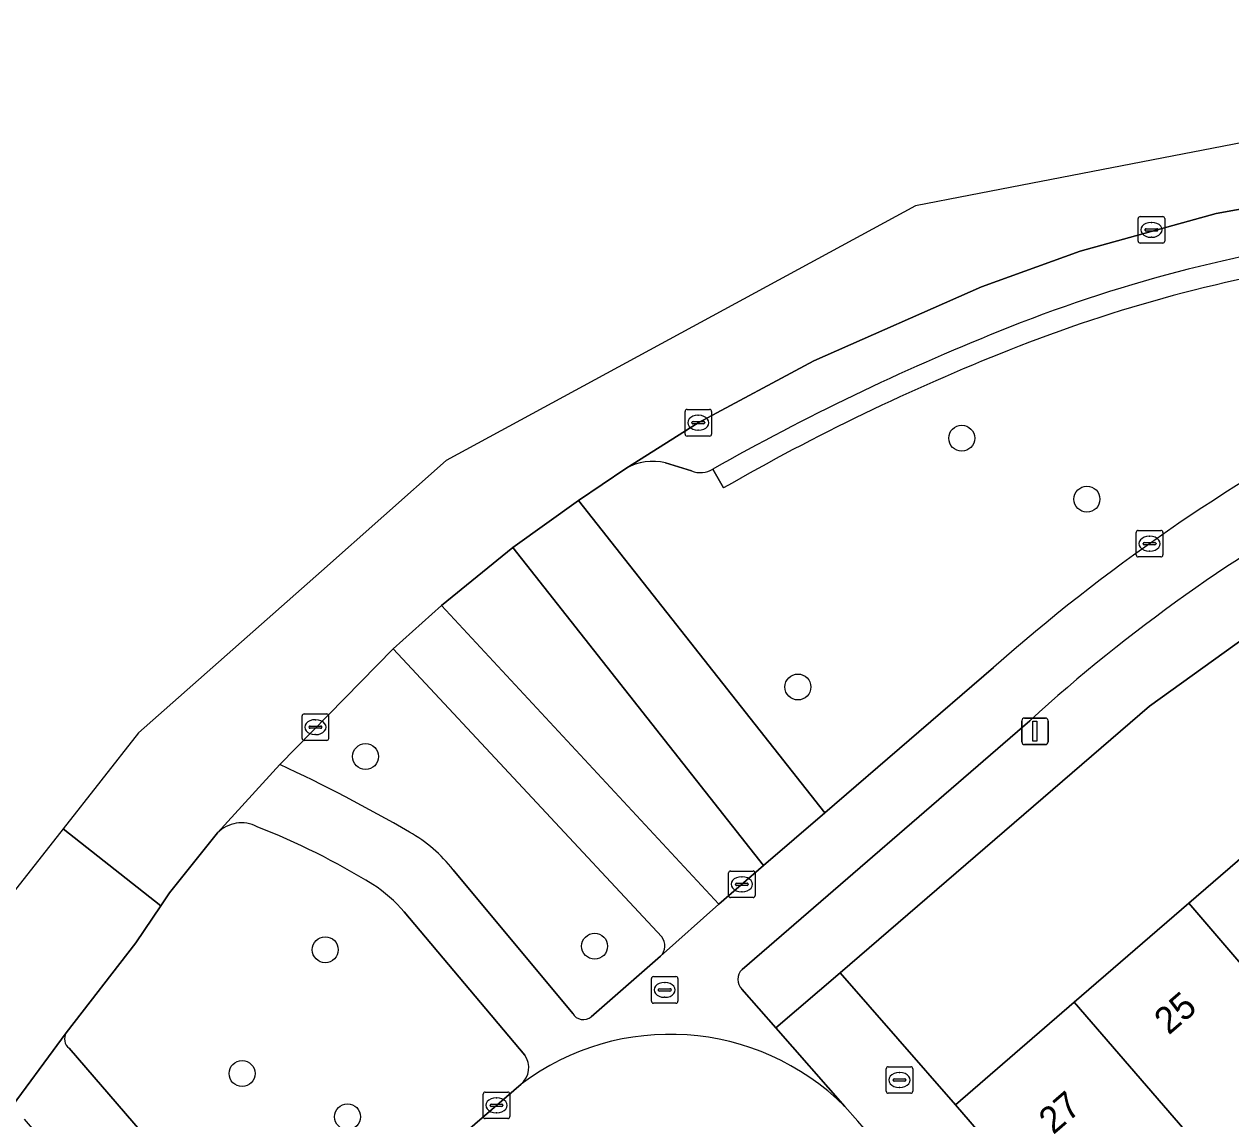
# Model space of a CAD drawing. Extents: x 160304 to 160955, y 383684 to 384161.
# Drawn here: x 160393.53 to 160439.02, y 384109.33 to 384150.58 of the extents above; entities that cross this region are included whole.
import ezdxf

# ---------------------------------------------------------------- set-up
doc = ezdxf.new("R2010")
doc.units = 0
for name, color, linetype in [('IMGEO_Berm_groen', 7, 'Continuous'), ('IMGEO_Berm_open', 7, 'Continuous'), ('IMGEO_Boom', 7, 'Continuous'), ('IMGEO_Brandkraan', 7, 'Continuous'), ('IMGEO_Erf', 7, 'Continuous'), ('IMGEO_Fietspad_open', 7, 'Continuous'), ('IMGEO_Kolk', 7, 'Continuous'), ('IMGEO_Lichtmast', 7, 'Continuous'), ('IMGEO_Pand', 7, 'Continuous'), ('IMGEO_Pand_nummerreeks', 7, 'Continuous'), ('IMGEO_Parkeervlak_open', 7, 'Continuous'), ('IMGEO_Rijbaan_lokaal_gesloten', 7, 'Continuous'), ('IMGEO_Rijbaan_lokaal_open', 7, 'Continuous'), ('IMGEO_Rioolput', 7, 'Continuous'), ('IMGEO_Verkeerseiland_open', 7, 'Continuous'), ('IMGEO_Voetpad_open', 7, 'Continuous')]:
    doc.layers.add(name, color=color, linetype=linetype)

msp = doc.modelspace()

# ---------------------------------------------------------------- linework, layer by layer
at = {"layer": 'IMGEO_Berm_groen'}
for points in [[(160416.214, 384133.836), (160414.425, 384132.626), (160423.714, 384120.862), (160430.072, 384126.329)], [(160418.69, 384133.741), (160417.711, 384134.04)], [(160419.892, 384133.098), (160419.489, 384133.811)], [(160407.44, 384127.034), (160403.169, 384122.675)], [(160417.57, 384116.188), (160407.44, 384127.034)], [(160400.821, 384120.099), (160399.013, 384117.842), (160398.679, 384117.35), (160397.736, 384115.959), (160395.112, 384112.569)], [(160409.698, 384118.709), (160414.209, 384113.298)], [(160412.402, 384111.722), (160407.855, 384117.121)], [(160414.91, 384113.169), (160417.523, 384115.457)], [(160395.225, 384111.986), (160403.163, 384102.78), (160412.264, 384110.636)]]:
    msp.add_lwpolyline(points, dxfattribs=at)
for centre, radius, start, end in [((160451.295, 384086.519), 55.733, 98.3238, 111.7235), ((160461.16, 384061.29), 82.822, 111.60326, 119.88602), ((160476.283, 384074.16), 69.692, 117.82068, 131.53435), ((160417.214, 384132.092), 2.011, 75.6932, 119.8269), ((160419.018, 384134.587), 0.908, 248.7894, 301.2243), ((160378.447, 384069.276), 58.845, 59.795, 65.15714), ((160401.721, 384119.229), 1.252, 62.0133, 135.9478), ((160392.248, 384094.642), 27.591, 58.4741, 68.6164), ((160405.469, 384115.476), 5.323, 37.3993, 60.9869), ((160403.581, 384113.461), 5.628, 40.5752, 56.6417), ((160417.133, 384115.849), 0.553, 314.8216, 37.8208), ((160414.615, 384113.533), 0.469, 210.1058, 309.0401), ((160395.498, 384112.341), 0.448, 149.4432, 232.4954), ((160411.747, 384111.253), 0.805, 309.923, 35.5933)]:
    msp.add_arc(centre, radius, start, end, dxfattribs=at)
at = {"layer": 'IMGEO_Berm_open'}
msp.add_lwpolyline([(160419.489, 384133.811), (160419.892, 384133.098)], dxfattribs=at)
for centre, radius, start, end in [((160451.061, 384087.716), 55.333, 97.4277, 112.0391), ((160451.295, 384086.519), 55.733, 98.3238, 111.7235), ((160464.378, 384054.254), 91.348, 111.90603, 119.43353), ((160461.16, 384061.29), 82.822, 111.60326, 119.88602)]:
    msp.add_arc(centre, radius, start, end, dxfattribs=at)
at = {"layer": 'IMGEO_Boom'}
for centre in [(160428.876, 384134.974), (160433.596, 384132.677), (160422.701, 384125.599), (160406.399, 384122.978), (160415.035, 384115.831), (160404.88, 384115.698), (160401.744, 384111.032), (160405.721, 384109.403)]:
    msp.add_circle(centre, 0.489, dxfattribs=at)
at = {"layer": 'IMGEO_Brandkraan'}
for p, q in [((160426.029, 384110.363), (160426.029, 384111.215)), ((160426.104, 384111.289), (160426.956, 384111.289)), ((160426.517, 384111.069), (160426.542, 384111.069)), ((160427.03, 384111.215), (160427.03, 384110.363)), ((160426.288, 384110.783), (160426.288, 384110.795)), ((160426.726, 384110.746), (160426.328, 384110.746)), ((160426.331, 384110.832), (160426.729, 384110.832)), ((160426.54, 384110.509), (160426.515, 384110.509)), ((160426.772, 384110.795), (160426.772, 384110.783)), ((160426.956, 384110.289), (160426.104, 384110.289))]:
    msp.add_line(p, q, dxfattribs=at)
for points in [[(160426.029, 384110.363), (160426.029, 384111.215)], [(160426.104, 384111.289), (160426.956, 384111.289)], [(160427.03, 384111.215), (160427.03, 384110.363)], [(160426.956, 384110.289), (160426.104, 384110.289)]]:
    msp.add_lwpolyline(points, dxfattribs=at)
for centre, radius, start, end in [((160426.106, 384111.213), 0.0765, 91.552, 178.448), ((160426.106, 384111.213), 0.0765, 91.552, 178.448), ((160426.954, 384111.213), 0.0765, 1.552, 88.448), ((160426.954, 384111.213), 0.0765, 1.552, 88.448), ((160426.328, 384110.792), 0.0403, 85.8775, 175.7526), ((160426.325, 384110.782), 0.0366, 178.938, 274.7102), ((160426.729, 384110.789), 0.043, 264.8664, 352.4533), ((160426.733, 384110.794), 0.0386, 1.7309, 96.639), ((160426.106, 384110.365), 0.0765, 181.552, 268.448), ((160426.106, 384110.365), 0.0765, 181.552, 268.448), ((160426.954, 384110.365), 0.0765, 271.552, 358.448), ((160426.954, 384110.365), 0.0765, 271.552, 358.448)]:
    msp.add_arc(centre, radius, start, end, dxfattribs=at)
for centre, major_axis, ratio, start_param, end_param in [((160426.516, 384110.789), (-0.387, 0.002), 0.722429, 4.712389, 7.853982), ((160426.541, 384110.789), (-0.39, 0.002), 0.717154, 1.570796, 4.712389)]:
    msp.add_ellipse(centre, major_axis=major_axis, ratio=ratio, start_param=start_param, end_param=end_param, dxfattribs=at)
at = {"layer": 'IMGEO_Erf'}
msp.add_lwpolyline([(160440.787, 384128.344), (160435.961, 384124.871), (160424.295, 384114.831), (160428.635, 384109.853), (160433.114, 384113.718), (160437.438, 384117.448), (160441.748, 384121.167)], dxfattribs=at)
at = {"layer": 'IMGEO_Fietspad_open'}
for points in [[(160430.072, 384126.329), (160423.714, 384120.862), (160421.405, 384118.867), (160419.712, 384117.417), (160417.523, 384115.457), (160414.91, 384113.169)], [(160420.593, 384114.949), (160431.449, 384124.329)], [(160403.169, 384122.675), (160400.821, 384120.099)], [(160414.209, 384113.298), (160409.698, 384118.709)], [(160407.855, 384117.121), (160412.402, 384111.722)], [(160424.465, 384109.796), (160421.87, 384112.754), (160420.589, 384114.214)]]:
    msp.add_lwpolyline(points, dxfattribs=at)
for centre, radius, start, end in [((160476.283, 384074.16), 69.692, 117.82068, 131.53435), ((160472.85, 384079.044), 61.358, 118.33433, 132.43502), ((160378.447, 384069.276), 58.845, 59.795, 65.15714), ((160401.721, 384119.229), 1.252, 62.0133, 135.9478), ((160392.248, 384094.642), 27.591, 58.4741, 68.6164), ((160405.469, 384115.476), 5.323, 37.3993, 60.9869), ((160403.581, 384113.461), 5.628, 40.5752, 56.6417), ((160420.933, 384114.58), 0.502, 132.6346, 226.7418), ((160414.615, 384113.533), 0.469, 210.1058, 309.0401), ((160417.879, 384103.166), 9.345, 45.1915, 126.9316), ((160411.747, 384111.253), 0.805, 309.923, 35.5933)]:
    msp.add_arc(centre, radius, start, end, dxfattribs=at)
at = {"layer": 'IMGEO_Kolk'}
for p, q in [((160435.526, 384142.399), (160435.526, 384143.251)), ((160435.601, 384143.325), (160436.453, 384143.325)), ((160436.527, 384143.251), (160436.527, 384142.399)), ((160435.785, 384142.819), (160435.785, 384142.831)), ((160436.223, 384142.782), (160435.825, 384142.782)), ((160435.828, 384142.868), (160436.226, 384142.868)), ((160436.014, 384143.105), (160436.039, 384143.105)), ((160436.269, 384142.831), (160436.269, 384142.819)), ((160436.453, 384142.325), (160435.601, 384142.325)), ((160436.037, 384142.545), (160436.012, 384142.545)), ((160418.444, 384135.131), (160418.444, 384135.983)), ((160418.519, 384136.057), (160419.371, 384136.057)), ((160419.445, 384135.983), (160419.445, 384135.131)), ((160418.703, 384135.551), (160418.703, 384135.563)), ((160419.141, 384135.514), (160418.743, 384135.514)), ((160418.746, 384135.6), (160419.144, 384135.6)), ((160418.932, 384135.837), (160418.957, 384135.837)), ((160419.187, 384135.563), (160419.187, 384135.551)), ((160419.371, 384135.057), (160418.519, 384135.057)), ((160418.955, 384135.277), (160418.93, 384135.277)), ((160435.458, 384130.574), (160435.458, 384131.426)), ((160435.533, 384131.5), (160436.385, 384131.5)), ((160436.459, 384131.426), (160436.459, 384130.574)), ((160435.717, 384130.994), (160435.717, 384131.006)), ((160436.155, 384130.957), (160435.757, 384130.957)), ((160435.76, 384131.043), (160436.158, 384131.043)), ((160435.946, 384131.28), (160435.971, 384131.28)), ((160436.201, 384131.006), (160436.201, 384130.994)), ((160436.385, 384130.5), (160435.533, 384130.5)), ((160435.969, 384130.72), (160435.944, 384130.72)), ((160404.007, 384123.659), (160404.007, 384124.511)), ((160404.082, 384124.585), (160404.934, 384124.585)), ((160405.008, 384124.511), (160405.008, 384123.659)), ((160404.266, 384124.079), (160404.266, 384124.091)), ((160404.309, 384124.128), (160404.707, 384124.128)), ((160404.495, 384124.365), (160404.52, 384124.365)), ((160404.75, 384124.091), (160404.75, 384124.079)), ((160404.704, 384124.042), (160404.306, 384124.042)), ((160404.518, 384123.805), (160404.493, 384123.805)), ((160404.934, 384123.585), (160404.082, 384123.585)), ((160420.085, 384117.739), (160420.085, 384118.591)), ((160420.16, 384118.665), (160421.012, 384118.665)), ((160421.086, 384118.591), (160421.086, 384117.739)), ((160420.344, 384118.159), (160420.344, 384118.171)), ((160420.387, 384118.208), (160420.785, 384118.208)), ((160420.573, 384118.445), (160420.598, 384118.445)), ((160420.828, 384118.171), (160420.828, 384118.159)), ((160420.782, 384118.122), (160420.384, 384118.122)), ((160420.596, 384117.885), (160420.571, 384117.885)), ((160421.012, 384117.665), (160420.16, 384117.665)), ((160410.834, 384109.409), (160410.834, 384110.261)), ((160410.909, 384110.335), (160411.761, 384110.335)), ((160411.322, 384110.115), (160411.347, 384110.115)), ((160411.835, 384110.261), (160411.835, 384109.409)), ((160411.093, 384109.829), (160411.093, 384109.841)), ((160411.531, 384109.792), (160411.133, 384109.792)), ((160411.136, 384109.878), (160411.534, 384109.878)), ((160411.345, 384109.555), (160411.32, 384109.555)), ((160411.577, 384109.841), (160411.577, 384109.829)), ((160411.761, 384109.335), (160410.909, 384109.335))]:
    msp.add_line(p, q, dxfattribs=at)
for points in [[(160435.526, 384142.399), (160435.526, 384143.251)], [(160435.601, 384143.325), (160436.453, 384143.325)], [(160436.527, 384143.251), (160436.527, 384142.399)], [(160436.453, 384142.325), (160435.601, 384142.325)], [(160418.444, 384135.131), (160418.444, 384135.983)], [(160418.519, 384136.057), (160419.371, 384136.057)], [(160419.445, 384135.983), (160419.445, 384135.131)], [(160419.371, 384135.057), (160418.519, 384135.057)], [(160435.458, 384130.574), (160435.458, 384131.426)], [(160435.533, 384131.5), (160436.385, 384131.5)], [(160436.459, 384131.426), (160436.459, 384130.574)], [(160436.385, 384130.5), (160435.533, 384130.5)], [(160404.007, 384123.659), (160404.007, 384124.511)], [(160404.082, 384124.585), (160404.934, 384124.585)], [(160405.008, 384124.511), (160405.008, 384123.659)], [(160404.934, 384123.585), (160404.082, 384123.585)], [(160420.085, 384117.739), (160420.085, 384118.591)], [(160420.16, 384118.665), (160421.012, 384118.665)], [(160421.086, 384118.591), (160421.086, 384117.739)], [(160421.012, 384117.665), (160420.16, 384117.665)], [(160410.834, 384109.409), (160410.834, 384110.261)], [(160410.909, 384110.335), (160411.761, 384110.335)], [(160411.835, 384110.261), (160411.835, 384109.409)], [(160411.761, 384109.335), (160410.909, 384109.335)]]:
    msp.add_lwpolyline(points, dxfattribs=at)
for centre, radius, start, end in [((160435.603, 384143.249), 0.0765, 91.552, 178.448), ((160435.603, 384143.249), 0.0765, 91.552, 178.448), ((160436.451, 384143.249), 0.0765, 1.552, 88.448), ((160436.451, 384143.249), 0.0765, 1.552, 88.448), ((160435.825, 384142.828), 0.0403, 85.8775, 175.7526), ((160435.822, 384142.818), 0.0366, 178.938, 274.7102), ((160436.226, 384142.825), 0.043, 264.8664, 352.4533), ((160436.23, 384142.83), 0.0386, 1.7309, 96.639), ((160435.603, 384142.401), 0.0765, 181.552, 268.448), ((160435.603, 384142.401), 0.0765, 181.552, 268.448), ((160436.451, 384142.401), 0.0765, 271.552, 358.448), ((160436.451, 384142.401), 0.0765, 271.552, 358.448), ((160418.521, 384135.981), 0.0765, 91.552, 178.448), ((160418.521, 384135.981), 0.0765, 91.552, 178.448), ((160419.369, 384135.981), 0.0765, 1.552, 88.448), ((160419.369, 384135.981), 0.0765, 1.552, 88.448), ((160418.743, 384135.56), 0.0403, 85.8775, 175.7526), ((160418.74, 384135.55), 0.0366, 178.938, 274.7102), ((160419.144, 384135.557), 0.043, 264.8664, 352.4533), ((160419.148, 384135.562), 0.0386, 1.7309, 96.639), ((160418.521, 384135.133), 0.0765, 181.552, 268.448), ((160418.521, 384135.133), 0.0765, 181.552, 268.448), ((160419.369, 384135.133), 0.0765, 271.552, 358.448), ((160419.369, 384135.133), 0.0765, 271.552, 358.448), ((160435.535, 384131.424), 0.0765, 91.552, 178.448), ((160435.535, 384131.424), 0.0765, 91.552, 178.448), ((160436.383, 384131.424), 0.0765, 1.552, 88.448), ((160436.383, 384131.424), 0.0765, 1.552, 88.448), ((160435.757, 384131.003), 0.0403, 85.8775, 175.7526), ((160435.754, 384130.993), 0.0366, 178.938, 274.7102), ((160436.158, 384131), 0.043, 264.8664, 352.4533), ((160436.162, 384131.005), 0.0386, 1.7309, 96.639), ((160435.535, 384130.576), 0.0765, 181.552, 268.448), ((160435.535, 384130.576), 0.0765, 181.552, 268.448), ((160436.383, 384130.576), 0.0765, 271.552, 358.448), ((160436.383, 384130.576), 0.0765, 271.552, 358.448), ((160404.084, 384124.509), 0.0765, 91.552, 178.448), ((160404.084, 384124.509), 0.0765, 91.552, 178.448), ((160404.932, 384124.509), 0.0765, 1.552, 88.448), ((160404.932, 384124.509), 0.0765, 1.552, 88.448), ((160404.306, 384124.088), 0.0403, 85.8775, 175.7526), ((160404.303, 384124.078), 0.0366, 178.938, 274.7102), ((160404.707, 384124.085), 0.043, 264.8664, 352.4533), ((160404.711, 384124.09), 0.0386, 1.7309, 96.639), ((160404.084, 384123.661), 0.0765, 181.552, 268.448), ((160404.084, 384123.661), 0.0765, 181.552, 268.448), ((160404.932, 384123.661), 0.0765, 271.552, 358.448), ((160404.932, 384123.661), 0.0765, 271.552, 358.448), ((160420.162, 384118.589), 0.0765, 91.552, 178.448), ((160420.162, 384118.589), 0.0765, 91.552, 178.448), ((160421.01, 384118.589), 0.0765, 1.552, 88.448), ((160421.01, 384118.589), 0.0765, 1.552, 88.448), ((160420.384, 384118.168), 0.0403, 85.8775, 175.7526), ((160420.381, 384118.158), 0.0366, 178.938, 274.7102), ((160420.785, 384118.165), 0.043, 264.8664, 352.4533), ((160420.789, 384118.17), 0.0386, 1.7309, 96.639), ((160420.162, 384117.741), 0.0765, 181.552, 268.448), ((160420.162, 384117.741), 0.0765, 181.552, 268.448), ((160421.01, 384117.741), 0.0765, 271.552, 358.448), ((160421.01, 384117.741), 0.0765, 271.552, 358.448), ((160410.911, 384110.259), 0.0765, 91.552, 178.448), ((160410.911, 384110.259), 0.0765, 91.552, 178.448), ((160411.759, 384110.259), 0.0765, 1.552, 88.448), ((160411.759, 384110.259), 0.0765, 1.552, 88.448), ((160411.133, 384109.838), 0.0403, 85.8775, 175.7526), ((160411.13, 384109.828), 0.0366, 178.938, 274.7102), ((160411.534, 384109.835), 0.043, 264.8664, 352.4533), ((160411.538, 384109.84), 0.0386, 1.7309, 96.639), ((160410.911, 384109.411), 0.0765, 181.552, 268.448), ((160410.911, 384109.411), 0.0765, 181.552, 268.448), ((160411.759, 384109.411), 0.0765, 271.552, 358.448), ((160411.759, 384109.411), 0.0765, 271.552, 358.448)]:
    msp.add_arc(centre, radius, start, end, dxfattribs=at)
for centre, major_axis, ratio, start_param, end_param in [((160436.013, 384142.825), (-0.387, 0.002), 0.722429, 4.712389, 7.853982), ((160436.038, 384142.825), (-0.39, 0.002), 0.717154, 1.570796, 4.712389), ((160418.931, 384135.557), (-0.387, 0.002), 0.722429, 4.712389, 7.853982), ((160418.956, 384135.557), (-0.39, 0.002), 0.717154, 1.570796, 4.712389), ((160435.945, 384131), (-0.387, 0.002), 0.722429, 4.712389, 7.853982), ((160435.97, 384131), (-0.39, 0.002), 0.717154, 1.570796, 4.712389), ((160404.494, 384124.085), (-0.387, 0.002), 0.722429, 4.712389, 7.853982), ((160404.519, 384124.085), (-0.39, 0.002), 0.717154, 1.570796, 4.712389), ((160420.572, 384118.165), (-0.387, 0.002), 0.722429, 4.712389, 7.853982), ((160420.597, 384118.165), (-0.39, 0.002), 0.717154, 1.570796, 4.712389), ((160411.321, 384109.835), (-0.387, 0.002), 0.722429, 4.712389, 7.853982), ((160411.346, 384109.835), (-0.39, 0.002), 0.717154, 1.570796, 4.712389)]:
    msp.add_ellipse(centre, major_axis=major_axis, ratio=ratio, start_param=start_param, end_param=end_param, dxfattribs=at)
at = {"layer": 'IMGEO_Lichtmast'}
for p, q in [((160431.141, 384123.53), (160431.141, 384124.33)), ((160431.141, 384124.33), (160431.141, 384123.53)), ((160431.241, 384124.43), (160432.031, 384124.43)), ((160432.031, 384124.43), (160431.241, 384124.43)), ((160432.131, 384124.33), (160432.131, 384123.53)), ((160432.131, 384123.53), (160432.131, 384124.33)), ((160432.031, 384123.43), (160431.241, 384123.43)), ((160431.241, 384123.43), (160432.031, 384123.43))]:
    msp.add_line(p, q, dxfattribs=at)
msp.add_lwpolyline([(160431.561, 384124.305), (160431.711, 384124.305), (160431.711, 384123.555), (160431.561, 384123.555), (160431.561, 384124.305)], dxfattribs=at)
for centre, start, end in [((160431.241, 384124.33), 90, 180), ((160431.241, 384124.33), 90, 180), ((160432.031, 384124.33), 0, 90), ((160432.031, 384124.33), 360, 90), ((160431.241, 384123.53), 180, 270), ((160431.241, 384123.53), 180, 270), ((160432.031, 384123.53), 270, 0), ((160432.031, 384123.53), 270, 0)]:
    msp.add_arc(centre, 0.1, start, end, dxfattribs=at)
at = {"layer": 'IMGEO_Pand'}
for points in [[(160447.183, 384114.851), (160441.748, 384121.167), (160437.438, 384117.448), (160442.868, 384111.128)], [(160437.438, 384117.448), (160433.114, 384113.718), (160438.563, 384107.413), (160440.506, 384105.161), (160444.812, 384108.876), (160442.868, 384111.128)], [(160433.114, 384113.718), (160428.635, 384109.853), (160434.079, 384103.544), (160437.865, 384106.811), (160438.563, 384107.413)]]:
    msp.add_lwpolyline(points, close=True, dxfattribs=at)
at = {"layer": 'IMGEO_Parkeervlak_open'}
for points in [[(160494.126, 384150.577), (160443.695, 384144.386), (160438.466, 384143.437), (160433.342, 384142.025), (160429.619, 384140.679), (160423.299, 384137.892), (160418.943, 384135.557), (160416.214, 384133.836)], [(160417.711, 384134.04), (160418.69, 384133.741)]]:
    msp.add_lwpolyline(points, dxfattribs=at)
for centre, radius, start, end in [((160451.061, 384087.716), 55.333, 97.4277, 112.0391), ((160464.378, 384054.254), 91.348, 111.90603, 119.43353), ((160417.214, 384132.092), 2.011, 75.6932, 119.8269), ((160419.018, 384134.587), 0.908, 248.7894, 301.2243)]:
    msp.add_arc(centre, radius, start, end, dxfattribs=at)
at = {"layer": 'IMGEO_Rijbaan_lokaal_gesloten'}
msp.add_lwpolyline([(160442.915, 384146.785), (160429.205, 384144.132), (160427.128, 384143.73), (160409.439, 384134.137), (160404.732, 384129.969), (160397.837, 384123.866), (160394.994, 384120.252), (160398.679, 384117.35), (160399.013, 384117.842), (160400.821, 384120.099), (160403.169, 384122.675), (160407.44, 384127.034), (160409.26, 384128.666), (160411.946, 384130.852), (160414.425, 384132.626), (160416.214, 384133.836), (160418.943, 384135.557), (160423.299, 384137.892), (160429.619, 384140.679), (160433.342, 384142.025), (160438.466, 384143.437), (160443.695, 384144.386)], dxfattribs=at)
msp.add_lwpolyline([(160394.994, 384120.252), (160387.672, 384110.946), (160391.585, 384107.888), (160392.757, 384109.377), (160395.112, 384112.569), (160397.736, 384115.959), (160398.679, 384117.35)], close=True, dxfattribs=at)
at = {"layer": 'IMGEO_Rijbaan_lokaal_open'}
for points in [[(160412.264, 384110.636), (160403.163, 384102.78), (160400.861, 384100.778), (160398.566, 384098.79), (160387.602, 384089.296), (160390.525, 384085.922), (160399.384, 384093.594), (160414.316, 384106.549)], [(160414.316, 384106.549), (160414.687, 384106.827), (160415.159, 384107.123), (160415.656, 384107.375), (160416.172, 384107.583), (160416.706, 384107.743), (160417.251, 384107.855), (160417.805, 384107.918), (160418.361, 384107.931), (160418.917, 384107.894), (160419.467, 384107.808), (160420.007, 384107.673), (160420.534, 384107.491), (160421.041, 384107.262), (160421.526, 384106.988), (160421.938, 384106.705), (160421.985, 384106.673), (160422.414, 384106.317), (160422.809, 384105.925), (160425.672, 384108.411), (160424.958, 384109.234), (160424.465, 384109.796)]]:
    msp.add_lwpolyline(points, dxfattribs=at)
msp.add_arc((160417.879, 384103.166), 9.345, 45.1915, 126.9316, dxfattribs=at)
at = {"layer": 'IMGEO_Rioolput'}
for p, q in [((160417.176, 384113.759), (160417.176, 384114.611)), ((160417.251, 384114.685), (160418.103, 384114.685)), ((160418.177, 384114.611), (160418.177, 384113.759)), ((160417.435, 384114.179), (160417.435, 384114.191)), ((160417.873, 384114.142), (160417.475, 384114.142)), ((160417.478, 384114.228), (160417.876, 384114.228)), ((160417.664, 384114.465), (160417.689, 384114.465)), ((160417.919, 384114.191), (160417.919, 384114.179)), ((160418.103, 384113.685), (160417.251, 384113.685)), ((160417.687, 384113.905), (160417.662, 384113.905))]:
    msp.add_line(p, q, dxfattribs=at)
for points in [[(160417.176, 384113.759), (160417.176, 384114.611)], [(160417.251, 384114.685), (160418.103, 384114.685)], [(160418.177, 384114.611), (160418.177, 384113.759)], [(160418.103, 384113.685), (160417.251, 384113.685)]]:
    msp.add_lwpolyline(points, dxfattribs=at)
for centre, radius, start, end in [((160417.253, 384114.609), 0.0765, 91.552, 178.448), ((160417.253, 384114.609), 0.0765, 91.552, 178.448), ((160418.101, 384114.609), 0.0765, 1.552, 88.448), ((160418.101, 384114.609), 0.0765, 1.552, 88.448), ((160417.475, 384114.188), 0.0403, 85.8775, 175.7526), ((160417.472, 384114.178), 0.0366, 178.938, 274.7102), ((160417.876, 384114.185), 0.043, 264.8664, 352.4533), ((160417.88, 384114.19), 0.0386, 1.7309, 96.639), ((160417.253, 384113.761), 0.0765, 181.552, 268.448), ((160417.253, 384113.761), 0.0765, 181.552, 268.448), ((160418.101, 384113.761), 0.0765, 271.552, 358.448), ((160418.101, 384113.761), 0.0765, 271.552, 358.448)]:
    msp.add_arc(centre, radius, start, end, dxfattribs=at)
for centre, major_axis, ratio, start_param, end_param in [((160417.663, 384114.185), (-0.387, 0.002), 0.722429, 4.712389, 7.853982), ((160417.688, 384114.185), (-0.39, 0.002), 0.717154, 1.570796, 4.712389)]:
    msp.add_ellipse(centre, major_axis=major_axis, ratio=ratio, start_param=start_param, end_param=end_param, dxfattribs=at)
at = {"layer": 'IMGEO_Verkeerseiland_open'}
msp.add_lwpolyline([(160409.26, 384128.666), (160419.712, 384117.417), (160421.405, 384118.867), (160411.946, 384130.852)], close=True, dxfattribs=at)
at = {"layer": 'IMGEO_Voetpad_open'}
msp.add_lwpolyline([(160414.425, 384132.626), (160411.946, 384130.852), (160421.405, 384118.867), (160423.714, 384120.862)], close=True, dxfattribs=at)
for points in [[(160409.26, 384128.666), (160407.44, 384127.034), (160417.57, 384116.188)], [(160417.523, 384115.457), (160419.712, 384117.417), (160409.26, 384128.666)], [(160420.589, 384114.214), (160421.87, 384112.754), (160424.295, 384114.831), (160435.961, 384124.871), (160440.787, 384128.344)], [(160431.449, 384124.329), (160420.593, 384114.949)], [(160442.101, 384094.34), (160439.748, 384097.068), (160434.079, 384103.544), (160428.635, 384109.853), (160424.295, 384114.831), (160421.87, 384112.754), (160424.465, 384109.796), (160424.958, 384109.234)], [(160395.112, 384112.569), (160392.757, 384109.377)], [(160393.527, 384109.316), (160398.923, 384103.034), (160400.861, 384100.778), (160403.163, 384102.78), (160395.225, 384111.986)]]:
    msp.add_lwpolyline(points, dxfattribs=at)
for centre, radius, start, end in [((160472.85, 384079.044), 61.358, 118.33433, 132.43502), ((160417.133, 384115.849), 0.553, 314.8216, 37.8208), ((160420.933, 384114.58), 0.502, 132.6346, 226.7418), ((160395.498, 384112.341), 0.448, 149.4432, 232.4954)]:
    msp.add_arc(centre, radius, start, end, dxfattribs=at)

# ---------------------------------------------------------------- texts
at = {"layer": 'IMGEO_Pand_nummerreeks'}
for s, rotation, p in [('25', 40.7882, (160436.68, 384112.461)), ('27', 40.7889, (160432.328, 384108.707))]:
    msp.add_text(s, height=1, rotation=rotation, dxfattribs=at).set_placement(p)

doc.saveas('drawing.dxf')
